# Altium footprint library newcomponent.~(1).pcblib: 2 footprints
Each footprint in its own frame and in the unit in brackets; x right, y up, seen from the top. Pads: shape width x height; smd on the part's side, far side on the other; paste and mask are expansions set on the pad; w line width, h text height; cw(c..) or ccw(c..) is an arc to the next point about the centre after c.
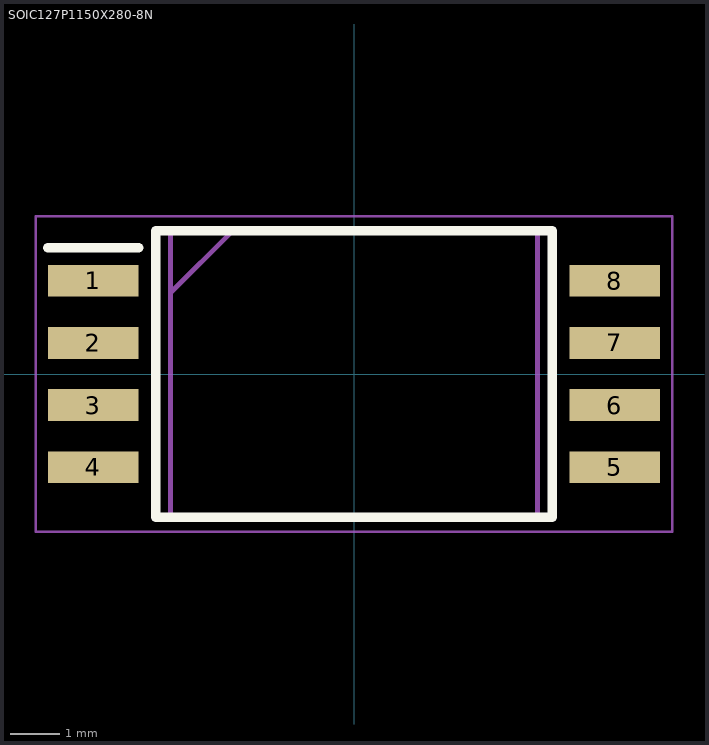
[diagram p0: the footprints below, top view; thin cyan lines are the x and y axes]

## PCBComponent_1 [mm]

## SOIC127P1150X280-8N [mm]
pads (8):
  rect 1.85x0.65 smd: 1(-5.325,1.905) 2(-5.325,0.635) 3(-5.325,-0.635) 4(-5.325,-1.905) 5(5.325,-1.905) 6(5.325,-0.635) 7(5.325,0.635) 8(5.325,1.905)
Top Overlay:
  lines w0.2: -6.25,2.58 -4.4,2.58 ; -4.05,-2.925 -4.05,2.925 4.05,2.925 4.05,-2.925 -4.05,-2.925
Mechanical 13:
  lines w0.1: -3.75,1.655 -2.48,2.925 ; -3.75,-2.925 -3.75,2.925 3.75,2.925 3.75,-2.925 -3.75,-2.925
Mechanical 15:
  lines w0.05: -6.5,-3.225 -6.5,3.225 6.5,3.225 6.5,-3.225 -6.5,-3.225
3D body "ISO1042BQDWVQ1.stp": height 2.8, standoff 0, extent -5.75,-2.925 5.75,2.925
